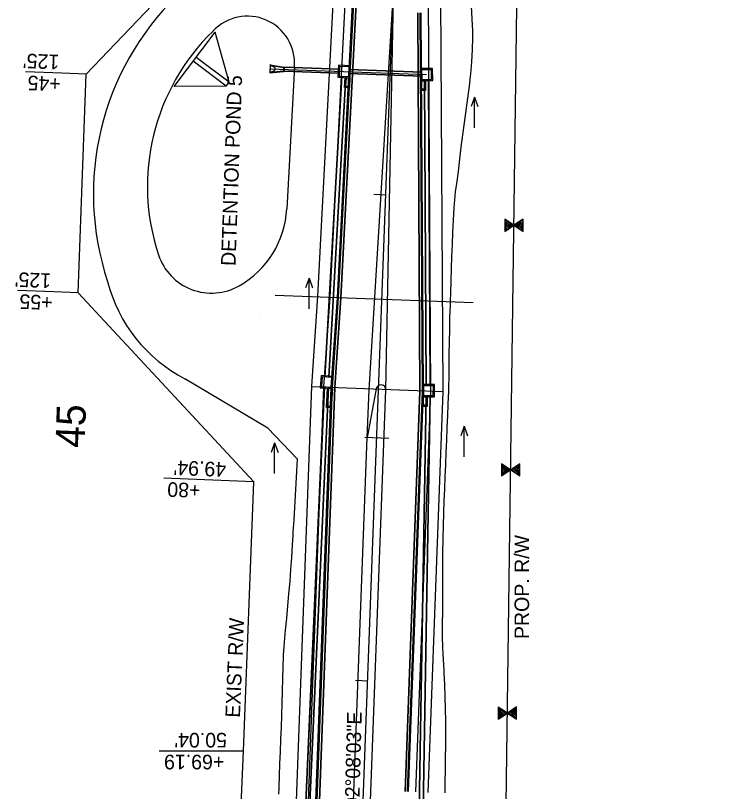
# Model space of a CAD drawing. Extents: x 670017 to 673226, y 705371 to 707498.
# Drawn here: x 671590.8 to 671881.1, y 706736.1 to 707055.2 of the extents above; entities that cross this region are included whole.
import ezdxf

# ---------------------------------------------------------------- set-up
doc = ezdxf.new("R2010")
doc.units = 0
for name, color, linetype in [('EL L SCBV', 7, 'Continuous'), ('EL R SCBV', 7, 'Continuous'), ('R_Drainage Flow Lines', 7, 'Continuous'), ('R_Drainage Stage 1', 7, 'Continuous'), ('R_Drainage Stage 1A', 7, 'Continuous'), ('R_Fence', 7, 'Continuous'), ('R_Horz Alg', 7, 'Continuous'), ('R_Horz Alg Station', 7, 'Continuous'), ('R_Horz Alg Station Annot', 7, 'Continuous'), ('R_Horz Bearing', 7, 'Continuous'), ('R_No Plot', 7, 'Continuous'), ('R_No Plot FOC', 7, 'Continuous'), ('R_Proposed Const Limits', 7, 'Continuous'), ('R_Proposed Const Limits Stage 1A', 7, 'Continuous'), ('R_Proposed Median', 7, 'Continuous'), ('R_Proposed Road', 7, 'Continuous'), ('R_Proposed Road Stage 1A', 7, 'Continuous'), ('R_Proposed Sidewalk Stage 1', 7, 'Continuous'), ('R_Proposed Sidewalk Stage 1A', 7, 'Continuous'), ('R_ROW', 7, 'Continuous'), ('R_ROW Annot', 7, 'Continuous'), ('R_Striping', 7, 'Continuous'), ('R_Water Annot', 7, 'Continuous'), ('S_EXIST_ROW', 7, 'Continuous')]:
    doc.layers.add(name, color=color, linetype=linetype)

# ---------------------------------------------------------------- blocks, each defined once
blk = doc.blocks.new('FLOW ARROW')
at = {"layer": 'R_Water Annot'}
for p, q in [((-12.57, 0), (0, 0)), ((0, 0), (-3.85, 1.4)), ((0, 0), (-3.85, -1.4))]:
    blk.add_line(p, q, dxfattribs=at)

msp = doc.modelspace()

# ---------------------------------------------------------------- linework, layer by layer
at = {"layer": 'EL L SCBV'}
for p, q in [((671731.31, 707067.02), (671724.66, 706939.18)), ((671724.66, 706939.18), (671722.16, 706902.23)), ((671722.16, 706902.25), (671715.06, 706711.75))]:
    msp.add_line(p, q, dxfattribs=at)
at = {"layer": 'EL R SCBV'}
for p, q in [((671756.2, 707056.32), (671757.13, 706900.72)), ((671757.13, 706900.72), (671750.99, 706736.09))]:
    msp.add_line(p, q, dxfattribs=at)
at = {"layer": 'R_Drainage Stage 1'}
for p, q in [((671757.86, 707030.09), (671727.94, 707031.2)), ((671757.86, 707030.26), (671727.95, 707031.37)), ((671757.85, 707031.76), (671728.03, 707032.87)), ((671757.85, 707031.92), (671728.04, 707033.04)), ((671759.7, 706902.95), (671758.95, 707028.93)), ((671759.87, 706902.95), (671759.11, 707028.93)), ((671761.37, 706902.93), (671760.61, 707028.94)), ((671761.53, 706902.93), (671760.78, 707028.94)), ((671756.25, 706694.69), (671759.68, 706898.95)), ((671756.42, 706694.71), (671759.85, 706898.95)), ((671757.92, 706694.94), (671761.34, 706898.93)), ((671758.09, 706694.97), (671761.51, 706898.93))]:
    msp.add_line(p, q, dxfattribs=at)
for points in [[(671762.37, 707028.45), (671762.34, 707033.45), (671757.34, 707033.42), (671757.37, 707028.42)], [(671761.86, 707028.94), (671761.84, 707032.94), (671757.84, 707032.92), (671757.86, 707028.92)], [(671759.37, 707028.43), (671759.39, 707024.43), (671757.39, 707024.42), (671757.37, 707028.42)], [(671758.87, 707028.43), (671758.89, 707024.93), (671757.89, 707024.92), (671757.87, 707028.42)], [(671763.1, 706898.41), (671763.16, 706903.41), (671758.16, 706903.47), (671758.1, 706898.47)], [(671762.6, 706898.91), (671762.65, 706902.91), (671758.65, 706902.97), (671758.6, 706898.97)], [(671760.1, 706898.45), (671760.04, 706894.45), (671758.04, 706894.47), (671758.1, 706898.47)], [(671759.6, 706898.45), (671759.55, 706894.95), (671758.55, 706894.97), (671758.6, 706898.47)]]:
    msp.add_lwpolyline(points, close=True, dxfattribs=at)
at = {"layer": 'R_Drainage Stage 1A'}
for p, q in [((671656.01, 707026.05), (671672.92, 707048.36)), ((671695.49, 707034.77), (671695.38, 707031.9)), ((671695.49, 707034.77), (671695.5, 707034.97)), ((671695.49, 707034.77), (671701.04, 707033.82)), ((671695.49, 707034.77), (671696.98, 707034.18)), ((671695.5, 707034.97), (671701.29, 707034.03)), ((671696.98, 707034.18), (671695.5, 707034.97)), ((671701.04, 707033.84), (671700.99, 707032.41)), ((671701.04, 707033.84), (671701.28, 707033.83)), ((671701.29, 707034.03), (671701.22, 707032.2)), ((671724.03, 707033.02), (671701.28, 707033.87)), ((671724.04, 707033.18), (671701.29, 707034.03)), ((671696.91, 707032.38), (671695.37, 707031.7)), ((671695.37, 707031.7), (671701.22, 707032.2)), ((671695.38, 707031.9), (671695.37, 707031.7)), ((671695.38, 707031.9), (671700.99, 707032.43)), ((671695.38, 707031.9), (671696.91, 707032.38)), ((671701.22, 707032.4), (671700.99, 707032.41)), ((671723.95, 707031.52), (671701.22, 707032.37)), ((671723.94, 707031.35), (671701.22, 707032.2)), ((671677.47, 707026.2), (671678.67, 707027.8)), ((671718, 706906.54), (671724.96, 707030.25)), ((671718.17, 706906.53), (671725.13, 707030.24)), ((671719.67, 706906.44), (671726.63, 707030.16)), ((671719.83, 706906.43), (671726.79, 707030.15)), ((671708.58, 706696.8), (671717.8, 706902.55)), ((671708.75, 706696.77), (671717.97, 706902.54)), ((671710.23, 706696.44), (671719.47, 706902.44)), ((671710.4, 706696.41), (671719.63, 706902.43))]:
    msp.add_line(p, q, dxfattribs=at)
for points in [[(671678.67, 707027.8), (671672.92, 707048.36)], [(671678.67, 707027.8), (671665.07, 707038)], [(671677.47, 707026.2), (671663.87, 707036.41)], [(671705.5, 707034.19), (671702.35, 706975.67)], [(671677.47, 707026.2), (671656.01, 707026.05)]]:
    msp.add_lwpolyline(points, dxfattribs=at)
for points in [[(671728.36, 707029.57), (671728.62, 707034.56), (671723.62, 707034.82), (671723.37, 707029.83)], [(671727.88, 707030.09), (671728.09, 707034.09), (671724.1, 707034.3), (671723.89, 707030.3)], [(671728.36, 707029.57), (671728.15, 707025.57), (671726.15, 707025.68), (671726.36, 707029.67)], [(671727.86, 707029.59), (671727.68, 707026.1), (671726.68, 707026.15), (671726.86, 707029.65)], [(671716.47, 706907.14), (671716.15, 706902.15), (671721.14, 706901.83), (671721.46, 706906.82)], [(671716.94, 706906.61), (671716.68, 706902.62), (671720.67, 706902.36), (671720.93, 706906.36)], [(671721.15, 706901.83), (671720.63, 706893.85), (671718.64, 706893.98), (671719.15, 706901.96)], [(671720.65, 706901.87), (671720.17, 706894.38), (671719.17, 706894.44), (671719.65, 706901.93)]]:
    msp.add_lwpolyline(points, close=True, dxfattribs=at)
for centre, radius, start, end in [((671686.19, 707035.62), 19.36, 355.7856, 137.0637), ((671734.14, 706984.93), 89.1, 134.2009, 198.3972), ((671696.63, 707033.29), 0.957, 287.2532, 68.4783), ((671663.66, 706977.75), 38.75, 299.591, 356.9246), ((671671.43, 706964.07), 23.01, 198.3972, 299.591)]:
    msp.add_arc(centre, radius, start, end, dxfattribs=at)
at = {"layer": 'R_Fence'}
for p, q in [((671795.03, 706968.43), (671792.02, 706971.41)), ((671794.61, 706968.15), (671792.03, 706970.7)), ((671795.46, 706968.72), (671794.12, 706970.04)), ((671799.54, 706968.19), (671797.57, 706970.14)), ((671799.54, 706968.9), (671797.99, 706970.43)), ((671799.53, 706969.61), (671798.41, 706970.71)), ((671799.53, 706970.31), (671798.84, 706971)), ((671799.52, 706971.02), (671799.26, 706971.28)), ((671794.19, 706967.86), (671792.03, 706969.99)), ((671793.76, 706967.58), (671792.03, 706969.29)), ((671793.34, 706967.29), (671792.04, 706968.58)), ((671792.92, 706967.01), (671792.04, 706967.87)), ((671792.5, 706966.72), (671792.05, 706967.16)), ((671796.25, 706968.64), (671795.88, 706969)), ((671798.38, 706967.24), (671796.3, 706969.29)), ((671799.55, 706966.78), (671796.72, 706969.57)), ((671799.55, 706967.49), (671797.15, 706969.86)), ((671792.07, 706966.43), (671792.05, 706966.46)), ((671793.69, 706867.86), (671790.68, 706870.84)), ((671793.27, 706867.57), (671790.68, 706870.13)), ((671792.85, 706867.29), (671790.69, 706869.42)), ((671792.42, 706867), (671790.69, 706868.71)), ((671792, 706866.72), (671790.7, 706868.01)), ((671794.11, 706868.15), (671792.78, 706869.47)), ((671794.9, 706868.07), (671794.54, 706868.43)), ((671797.03, 706866.66), (671794.96, 706868.72)), ((671798.21, 706866.21), (671795.38, 706869)), ((671798.2, 706866.91), (671795.8, 706869.29)), ((671798.2, 706867.62), (671796.23, 706869.57)), ((671798.2, 706868.33), (671796.65, 706869.86)), ((671798.19, 706869.04), (671797.07, 706870.14)), ((671798.19, 706869.74), (671797.49, 706870.43)), ((671798.18, 706870.45), (671797.92, 706870.71)), ((671791.58, 706866.43), (671790.7, 706867.3)), ((671791.16, 706866.15), (671790.71, 706866.59)), ((671790.73, 706865.86), (671790.71, 706865.89)), ((671792.36, 706767.83), (671789.35, 706770.8)), ((671791.93, 706767.54), (671789.35, 706770.1)), ((671791.51, 706767.26), (671789.35, 706769.39)), ((671792.78, 706768.11), (671791.44, 706769.44)), ((671796.87, 706766.17), (671794.05, 706768.97)), ((671796.87, 706766.88), (671794.47, 706769.25)), ((671796.86, 706767.59), (671794.89, 706769.54)), ((671796.86, 706768.3), (671795.31, 706769.82)), ((671796.86, 706769), (671795.74, 706770.11)), ((671796.85, 706769.71), (671796.16, 706770.39)), ((671796.85, 706770.42), (671796.58, 706770.68)), ((671791.09, 706766.97), (671789.36, 706768.68)), ((671790.67, 706766.69), (671789.36, 706767.97)), ((671790.24, 706766.4), (671789.37, 706767.27)), ((671789.82, 706766.12), (671789.37, 706766.56)), ((671789.4, 706765.83), (671789.37, 706765.85)), ((671793.57, 706768.03), (671793.2, 706768.4)), ((671795.7, 706766.63), (671793.62, 706768.68))]:
    msp.add_line(p, q, dxfattribs=at)
for points in [[(671795.78, 706968.94), (671795.79, 706968.94), (671799.55, 706966.46), (671799.52, 706971.46), (671795.79, 706968.95), (671795.78, 706968.95), (671792.02, 706971.42), (671792.05, 706966.42), (671795.78, 706968.94)], [(671794.44, 706868.36), (671794.45, 706868.36), (671798.21, 706865.89), (671798.18, 706870.89), (671794.45, 706868.37), (671794.44, 706868.37), (671790.68, 706870.85), (671790.71, 706865.85), (671794.44, 706868.36)], [(671793.1, 706768.33), (671793.12, 706768.33), (671796.87, 706765.86), (671796.85, 706770.86), (671793.12, 706768.34), (671793.1, 706768.34), (671789.35, 706770.81), (671789.37, 706765.81), (671793.1, 706768.33)]]:
    msp.add_lwpolyline(points, dxfattribs=at)
at = {"layer": 'R_Horz Alg'}
msp.add_line((671726.73, 706541.35), (671758.33, 707389.39), dxfattribs=at)
at = {"layer": 'R_Horz Alg Station'}
for points in [[(671738.13, 706981.71), (671743.13, 706981.52)], [(671740.63, 706981.61), (671743.13, 706981.52)], [(671734.41, 706881.78), (671744.4, 706881.4)], [(671734.41, 706881.78), (671744.4, 706881.4)], [(671730.68, 706781.85), (671735.68, 706781.66)], [(671733.18, 706781.75), (671735.68, 706781.66)]]:
    msp.add_lwpolyline(points, dxfattribs=at)
at = {"layer": 'R_No Plot'}
for points in [[(672600.73, 706535.93), (672600.73, 706535.93), (672146.36, 706559.78), (671852.81, 706595.21), (671791.92, 706679.49), (671797.39, 707089.58)], [(671695.44, 707033.33), (671759.85, 707030.93)], [(671697.64, 706940.19), (671779.06, 706937.15)], [(671712.69, 706902.6), (671766.88, 706900.58)]]:
    msp.add_lwpolyline(points, dxfattribs=at)
at = {"layer": 'R_No Plot FOC'}
for p, q in [((671723.66, 706939.23), (671730.31, 707067.07)), ((671758.13, 706900.73), (671757.2, 707056.32)), ((671721.16, 706902.3), (671723.66, 706939.22)), ((671714.06, 706711.79), (671721.16, 706902.28)), ((671751.99, 706736.05), (671758.13, 706900.68))]:
    msp.add_line(p, q, dxfattribs=at)
at = {"layer": 'R_Proposed Const Limits'}
for points in [[(671767.51, 706735.48), (671767.54, 706739.96), (671767.64, 706744.96), (671767.71, 706749.96), (671767.75, 706754.97), (671767.78, 706759.97), (671767.74, 706764.97), (671767.62, 706769.98), (671767.48, 706774.99), (671767.3, 706780), (671767.08, 706785.01), (671767.06, 706785.49), (671766.9, 706788.76), (671766.84, 706790.02), (671766.7, 706793.14), (671766.61, 706795.04), (671766.45, 706800.05), (671766.47, 706805.05), (671766.49, 706810.05), (671766.51, 706815.05), (671766.52, 706820.06), (671766.54, 706825.06), (671766.52, 706830.06), (671766.5, 706835.07), (671766.62, 706839.09), (671766.65, 706840.07), (671766.67, 706840.55), (671766.83, 706845.54), (671766.99, 706850.54), (671767.15, 706855.54), (671767.34, 706860.54), (671767.56, 706865.53), (671767.77, 706870.53), (671767.97, 706875.52), (671768.16, 706880.52), (671768.35, 706885.52), (671768.46, 706888.33), (671768.54, 706890.51), (671768.74, 706895.51), (671769.03, 706900.79), (671769.04, 706901), (671769.04, 706901.01), (671769.04, 706901.24), (671769.05, 706903.02), (671769.09, 706906.02), (671769.14, 706911.02), (671769.21, 706916.03), (671769.29, 706921.04), (671769.38, 706926.04), (671769.49, 706931.05), (671769.65, 706936.05), (671769.67, 706936.73), (671769.73, 706938.05), (671769.82, 706941.06), (671769.97, 706946.06), (671770.13, 706951.07), (671770.31, 706956.07), (671770.5, 706961.08), (671770.71, 706966.09), (671770.93, 706971.09), (671771.21, 706976.1), (671771.59, 706981.11), (671771.81, 706982.72), (671772.27, 706986.11), (671772.94, 706991.12), (671773.52, 706996.13), (671774.13, 707001.14), (671774.77, 707006.15), (671775.43, 707011.16), (671776.1, 707016.17), (671776.79, 707021.18), (671777.49, 707026.18), (671777.97, 707030.21), (671778.07, 707031.19), (671778.51, 707036.2), (671778.8, 707041.21), (671778.87, 707046.21), (671778.82, 707049.21), (671778.79, 707051.22), (671778.13, 707061.87)], [(671691.23, 706931.62), (671691.23, 706931.62)]]:
    msp.add_lwpolyline(points, dxfattribs=at)
msp.add_arc((671701.13, 706981.28), 50.64, 258.7356, 258.7356, dxfattribs=at)
at = {"layer": 'R_Proposed Const Limits Stage 1A'}
msp.add_lwpolyline([(671699.12, 706735), (671699.21, 706737.51), (671699.23, 706738.02), (671699.39, 706742.5), (671699.57, 706747.5), (671699.76, 706752.5), (671699.95, 706757.49), (671700.17, 706762.49), (671700.36, 706767.48), (671700.45, 706772.48), (671700.56, 706777.48), (671700.68, 706782.48), (671700.83, 706787.48), (671700.85, 706787.96), (671700.95, 706791.22), (671700.99, 706792.48), (671701.24, 706795.58), (671701.41, 706797.47), (671701.87, 706802.45), (671702.33, 706807.44), (671702.79, 706812.43), (671703.25, 706817.41), (671703.71, 706822.4), (671704.08, 706827.39), (671704.39, 706832.38), (671704.7, 706837.37), (671704.95, 706841.39), (671705.01, 706842.36), (671705.04, 706842.84), (671705.35, 706847.84), (671705.64, 706852.83), (671705.94, 706857.82), (671706.23, 706862.81), (671706.52, 706867.81), (671706.79, 706872.8), (671694.57, 706885.45), (671660.44, 706905.84)], dxfattribs=at)
for centre, radius, start, end in [((671736.94, 706981.8), 114.1, 134.4692, 198.3972), ((671689.25, 706961.36), 62.54, 194.4128, 242.5784)]:
    msp.add_arc(centre, radius, start, end, dxfattribs=at)
at = {"layer": 'R_Proposed Median'}
for p, q in [((671739.18, 706901.69), (671735.41, 706881.66)), ((671736.17, 706714.12), (671743.14, 706901.24)), ((671728.37, 706692.88), (671735.41, 706881.66))]:
    msp.add_line(p, q, dxfattribs=at)
msp.add_arc((671741.14, 706901.32), 2, 357.8657, 169.335, dxfattribs=at)
at = {"layer": 'R_Proposed Road'}
for p, q in [((671757.13, 706900.72), (671756.2, 707056.32)), ((671758.63, 706900.73), (671757.7, 707056.32)), ((671750.99, 706736.09), (671757.13, 706900.72)), ((671752.49, 706736.04), (671758.63, 706900.66))]:
    msp.add_line(p, q, dxfattribs=at)
at = {"layer": 'R_Proposed Road Stage 1A'}
for p, q in [((671723.17, 706939.26), (671729.81, 707067.1)), ((671724.66, 706939.18), (671731.31, 707067.02)), ((671720.66, 706902.33), (671723.16, 706939.24)), ((671722.16, 706902.23), (671724.66, 706939.18)), ((671713.56, 706711.8), (671720.66, 706902.3)), ((671715.06, 706711.75), (671722.16, 706902.25))]:
    msp.add_line(p, q, dxfattribs=at)
at = {"layer": 'R_Proposed Sidewalk Stage 1'}
for p, q in [((671761.63, 706900.65), (671760.66, 707064.28)), ((671766.63, 706900.57), (671765.65, 707065.73)), ((671755.49, 706735.92), (671761.63, 706900.65)), ((671760.49, 706735.74), (671766.63, 706900.57))]:
    msp.add_line(p, q, dxfattribs=at)
at = {"layer": 'R_Proposed Sidewalk Stage 1A'}
for p, q in [((671715.18, 706939.75), (671721.75, 707066.16)), ((671720.17, 706939.45), (671726.74, 707065.9)), ((671712.67, 706902.74), (671715.18, 706939.75)), ((671717.67, 706902.48), (671720.17, 706939.45)), ((671705.57, 706712.1), (671712.67, 706902.74)), ((671710.57, 706711.92), (671717.67, 706902.48))]:
    msp.add_line(p, q, dxfattribs=at)
at = {"layer": 'R_ROW'}
for points in [[(671688.75, 706863.46), (671616.54, 706941.21), (671619.89, 707031.15), (671698.29, 707113.28)], [(672600.73, 706535.93), (672600.73, 706535.93), (672146.36, 706559.78), (671852.81, 706595.21), (671791.92, 706679.49), (671797.39, 707089.58)]]:
    msp.add_lwpolyline(points, dxfattribs=at)
at = {"layer": 'R_ROW Annot'}
for points in [[(671619.89, 707031.15), (671609.9, 707031.52), (671594.91, 707032.08)], [(671616.54, 706941.21), (671606.55, 706941.58), (671591.56, 706942.14)], [(671688.75, 706863.46), (671661.85, 706864.53), (671651.86, 706864.9)], [(671684.53, 706752.74), (671669.83, 706752.72), (671649.83, 706752.72)]]:
    msp.add_lwpolyline(points, dxfattribs=at)
at = {"layer": 'R_Striping'}
for p, q in [((671736.27, 706901.3), (671746.29, 707066.46)), ((671743.14, 706901.24), (671746.29, 707066.46)), ((671735.42, 706881.74), (671736.27, 706901.3))]:
    msp.add_line(p, q, dxfattribs=at)
at = {"layer": 'S_EXIST_ROW'}
msp.add_lwpolyline([(671682.63, 706708.58), (671684.53, 706752.74), (671688.75, 706863.46)], dxfattribs=at)

# ---------------------------------------------------------------- block references
at = {"layer": 'R_Drainage Flow Lines', "rotation": 89.99999999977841}
for p in [(671779.53, 707021.61), (671711.51, 706947.14), (671775.29, 706886.27), (671697.38, 706879.42)]:
    msp.add_blockref('FLOW ARROW', p, dxfattribs=at)

# ---------------------------------------------------------------- texts
at = {"layer": 'R_Horz Alg Station Annot'}
msp.add_text('45', height=12, rotation=87.8657, dxfattribs=at).set_placement((671619.16, 706877.28))
at = {"layer": 'R_Horz Bearing'}
msp.add_text('N02%%d08\'03"E', height=6, rotation=88.5162, dxfattribs=at).set_placement((671732.03, 706723.36))
at = {"layer": 'R_ROW Annot'}
for s, rotation, p in [("125'", 177.8657, (671608.88, 707039.06)), ('+45', 177.8657, (671609.49, 707030.03)), ('DETENTION POND 5', 87.9849, (671681.26, 706952.15)), ("125'", 177.8657, (671605.53, 706949.12)), ('+55', 177.8657, (671606.14, 706940.09)), ("49.94'", 177.8657, (671677.54, 706871.45)), ('+80', 177.8657, (671666.96, 706862.83)), ('PROP. R/W', 90, (671802.03, 706798.8)), ('EXIST R/W', 87.6273, (671683.09, 706766.36)), ("50.04'", 180, (671677.75, 706760.2)), ('+69.19', 180, (671676.67, 706751.2))]:
    msp.add_text(s, height=6, rotation=rotation, dxfattribs=at).set_placement(p)

doc.saveas('drawing.dxf')
